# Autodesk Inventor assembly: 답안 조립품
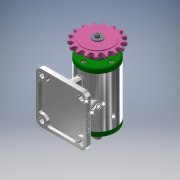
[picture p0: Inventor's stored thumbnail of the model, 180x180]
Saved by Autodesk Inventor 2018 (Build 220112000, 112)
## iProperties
Created: 2019-06
Part Number: 답안 조립품
Document SubType Name: Assembly
Designer: Administrator
Author: Administrator
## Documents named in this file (11)
- C:\Users\Administrator\Desktop\490604V1041\답안 조립품.iam
- C:\Users\Administrator\Desktop\490604V1041\본체.ipt
- C:\Users\Administrator\Desktop\490604V1041\베어링 6203.ipt
- C:\Users\Administrator\Desktop\490604V1041\볼트 M4.ipt
- C:\Users\Administrator\Desktop\490604V1041\오일 실 17 30 5.ipt
- C:\Users\Administrator\Desktop\490604V1041\스프로킷.ipt
- C:\Users\Administrator\Desktop\490604V1041\스프링와셔.ipt
- C:\Users\Administrator\Desktop\490604V1041\커버.ipt
- C:\Users\Administrator\Desktop\490604V1041\키 4x4x12.ipt
- C:\Users\Administrator\Desktop\490604V1041\축.ipt
- C:\Users\Administrator\Desktop\490604V1041\평와셔.ipt
